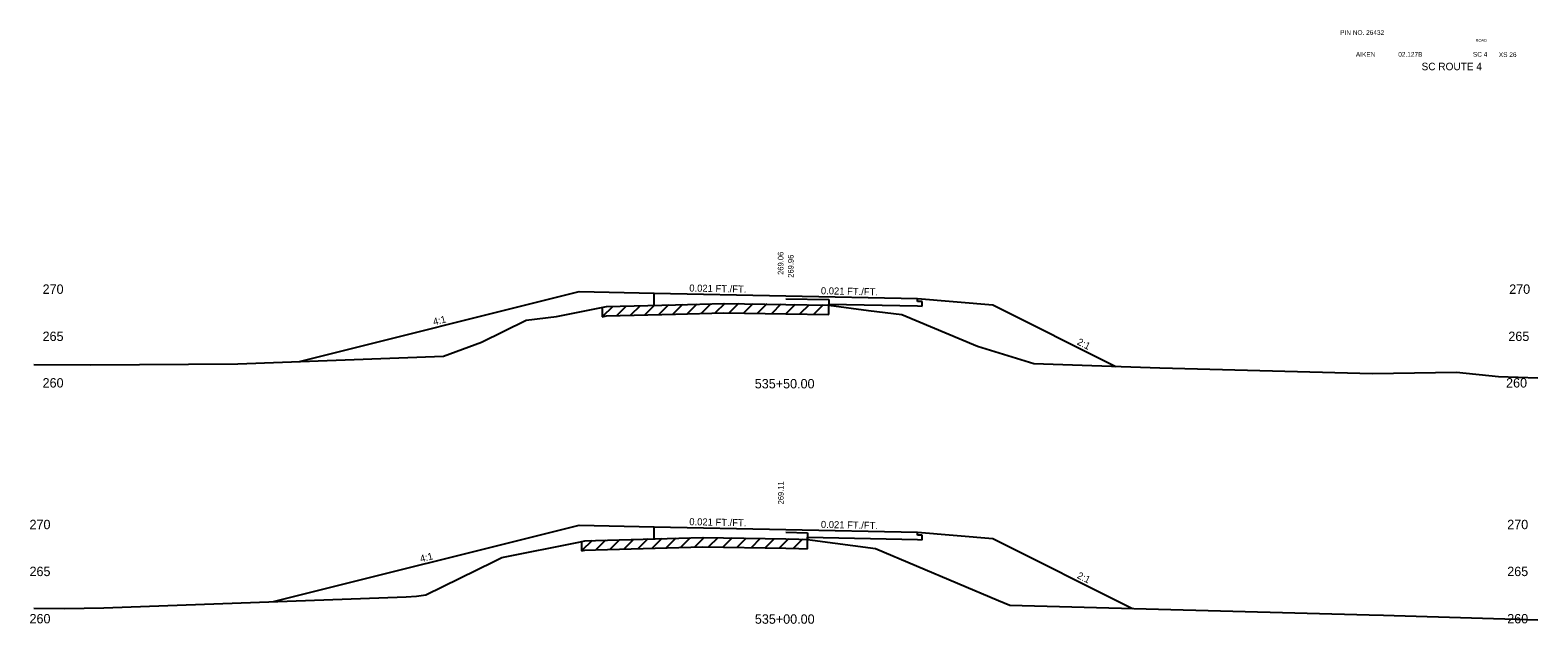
# Model space of a CAD drawing. Extents: x 883 to 1160, y 1002 to 4323.
# Drawn here: x 999.6 to 1160, y 3915.1 to 3978.2 of the extents above; entities that cross this region are included whole.
import ezdxf

# ---------------------------------------------------------------- set-up
doc = ezdxf.new("R2010")
doc.units = 0
for name, color, linetype in [('Level 1', 7, 'Continuous'), ('Level 10', 7, 'Continuous'), ('Level 11', 7, 'Continuous'), ('Level 12', 7, 'Continuous'), ('Level 3', 7, 'Continuous'), ('Level 32', 7, 'Continuous'), ('Level 53', 7, 'Continuous'), ('Level 59', 7, 'Continuous'), ('Level 6', 7, 'Continuous'), ('Level 60', 7, 'Continuous'), ('Level 61', 7, 'Continuous'), ('Level 7', 7, 'Continuous')]:
    doc.layers.add(name, color=color, linetype=linetype)

msp = doc.modelspace()

# ---------------------------------------------------------------- linework, layer by layer
at = {"layer": 'Level 11'}
for p, q in [((1066, 3948.96), (1066, 3950.26)), ((1094, 3949.37), (1094, 3949.67)), ((1094.5, 3949.36), (1094, 3949.37)), ((1094.5, 3948.88), (1094.5, 3949.36)), ((1094, 3948.89), (1094.5, 3948.88)), ((1066, 3924.12), (1066, 3925.4)), ((1094, 3924.52), (1094, 3924.82)), ((1094.5, 3924.5), (1094, 3924.52)), ((1094, 3924.04), (1094.5, 3924.02)), ((1094.5, 3924.02), (1094.5, 3924.5))]:
    msp.add_line(p, q, dxfattribs=at)
at = {"layer": 'Level 12'}
for p, q in [((1084.57, 3948.99), (1084.57, 3949.09)), ((1084.57, 3949.09), (1094, 3948.89)), ((1082.31, 3924.06), (1082.31, 3924.28)), ((1082.31, 3924.28), (1094, 3924.04))]:
    msp.add_line(p, q, dxfattribs=at)
at = {"layer": 'Level 53'}
for p, q in [((1080, 3949.66), (1084.57, 3949.57)), ((1084.57, 3949.57), (1084.57, 3948.99)), ((1080, 3924.81), (1082.31, 3924.76)), ((1082.31, 3924.76), (1082.31, 3924.06))]:
    msp.add_line(p, q, dxfattribs=at)
at = {"layer": 'Level 59'}
for p, q in [((1066, 3950.26), (1080, 3949.96)), ((1080, 3949.96), (1094, 3949.67)), ((1066, 3925.4), (1080, 3925.11)), ((1080, 3925.11), (1094, 3924.82))]:
    msp.add_line(p, q, dxfattribs=at)
at = {"layer": 'Level 6'}
for p, q in [((1058, 3950.42), (1066, 3950.26)), ((1094, 3949.67), (1102, 3949.01)), ((1058, 3925.56), (1066, 3925.4)), ((1094, 3924.82), (1102, 3924.15))]:
    msp.add_line(p, q, dxfattribs=at)
at = {"layer": 'Level 60'}
for p, q in [((1068.25, 3949.02), (1073.41, 3949.17)), ((1073.41, 3949.17), (1080, 3949.06)), ((1052.38, 3947.37), (1055.59, 3947.76)), ((1055.59, 3947.76), (1060.9, 3948.83)), ((1060.9, 3948.83), (1068.25, 3949.02)), ((1080, 3949.06), (1084.58, 3948.99)), ((1084.58, 3948.99), (1088.78, 3948.42)), ((1088.78, 3948.42), (1092.35, 3947.98)), ((1092.35, 3947.98), (1100.37, 3944.61)), ((1047.62, 3945.05), (1052.38, 3947.37)), ((1043.56, 3943.55), (1047.62, 3945.05)), ((1100.37, 3944.61), (1106.37, 3942.77)), ((1000, 3942.67), (1006, 3942.62)), ((1006, 3942.62), (1021.69, 3942.75)), ((1021.69, 3942.75), (1043.56, 3943.55)), ((1106.37, 3942.77), (1119.78, 3942.3)), ((1119.78, 3942.3), (1142.41, 3941.69)), ((1142.41, 3941.69), (1151.34, 3941.83)), ((1151.34, 3941.83), (1155.83, 3941.38)), ((1155.83, 3941.38), (1160, 3941.26)), ((1049.78, 3922.12), (1057.99, 3923.76)), ((1057.99, 3923.76), (1058.6, 3923.91)), ((1058.6, 3923.91), (1059.73, 3923.95)), ((1059.73, 3923.95), (1071.18, 3924.26)), ((1071.18, 3924.26), (1080, 3924.11)), ((1080, 3924.11), (1081.39, 3924.08)), ((1081.39, 3924.08), (1082.3, 3924.06)), ((1082.3, 3924.06), (1082.84, 3923.98)), ((1082.84, 3923.98), (1089.55, 3923.07)), ((1048.93, 3921.7), (1049.78, 3922.12)), ((1089.55, 3923.07), (1102.62, 3917.57)), ((1041.68, 3918.17), (1048.93, 3921.7)), ((1007.44, 3916.77), (1039.6, 3917.96)), ((1039.6, 3917.96), (1040.69, 3918.01)), ((1040.69, 3918.01), (1041.68, 3918.17)), ((1102.62, 3917.57), (1103.84, 3917.05)), ((1103.84, 3917.05), (1142.07, 3916.04)), ((1000, 3916.73), (1003.26, 3916.71)), ((1003.26, 3916.71), (1007.44, 3916.77)), ((1142.07, 3916.04), (1143.58, 3915.98)), ((1143.58, 3915.98), (1144.72, 3915.97)), ((1144.72, 3915.97), (1160, 3915.51))]:
    msp.add_line(p, q, dxfattribs=at)
at = {"layer": 'Level 61'}
for p, q in [((1070.51, 3949.09), (1069.48, 3948.06)), ((1072.01, 3949.13), (1070.98, 3948.1)), ((1073.51, 3949.17), (1072.48, 3948.15)), ((1074.97, 3949.15), (1073.98, 3948.16)), ((1076.47, 3949.12), (1075.49, 3948.14)), ((1077.97, 3949.1), (1076.99, 3948.11)), ((1079.47, 3949.07), (1078.49, 3948.09)), ((1061.58, 3948.84), (1060.47, 3947.74)), ((1060.47, 3948.74), (1060.47, 3947.74)), ((1060.47, 3947.74), (1060.9, 3947.83)), ((1060.9, 3947.83), (1068.25, 3948.02)), ((1063, 3948.88), (1061.97, 3947.85)), ((1064.5, 3948.92), (1063.48, 3947.9)), ((1066.01, 3948.96), (1064.98, 3947.94)), ((1067.51, 3949), (1066.48, 3947.98)), ((1069.01, 3949.05), (1067.98, 3948.02)), ((1068.25, 3948.02), (1073.41, 3948.17)), ((1073.41, 3948.17), (1080, 3948.06)), ((1080.97, 3949.04), (1079.99, 3948.06)), ((1080, 3948.06), (1084.57, 3947.99)), ((1082.48, 3949.02), (1081.49, 3948.04)), ((1083.98, 3949), (1082.99, 3948.01)), ((1084.57, 3947.99), (1084.57, 3948.99)), ((1059.38, 3923.94), (1058.27, 3922.83)), ((1058.27, 3923.83), (1058.27, 3922.83)), ((1060.8, 3923.98), (1059.77, 3922.95)), ((1062.3, 3924.02), (1061.27, 3922.99)), ((1063.8, 3924.06), (1062.77, 3923.03)), ((1065.3, 3924.1), (1064.27, 3923.07)), ((1066.8, 3924.14), (1065.77, 3923.11)), ((1068.3, 3924.18), (1067.28, 3923.15)), ((1069.81, 3924.22), (1068.78, 3923.19)), ((1071.3, 3924.26), (1070.28, 3923.24)), ((1072.76, 3924.23), (1071.78, 3923.25)), ((1074.27, 3924.21), (1073.28, 3923.22)), ((1075.77, 3924.18), (1074.78, 3923.2)), ((1077.27, 3924.15), (1076.29, 3923.17)), ((1078.77, 3924.13), (1077.79, 3923.15)), ((1080.27, 3924.1), (1079.29, 3923.12)), ((1081.77, 3924.07), (1080.79, 3923.09)), ((1082.31, 3923.06), (1082.31, 3924.06)), ((1058.27, 3922.83), (1058.6, 3922.91)), ((1058.6, 3922.91), (1059.73, 3922.95)), ((1059.73, 3922.95), (1071.18, 3923.26)), ((1071.18, 3923.26), (1080, 3923.11)), ((1080, 3923.11), (1081.39, 3923.08)), ((1081.39, 3923.08), (1082.3, 3923.06)), ((1082.3, 3923.06), (1082.31, 3923.06))]:
    msp.add_line(p, q, dxfattribs=at)
at = {"layer": 'Level 7'}
for p, q in [((1028.27, 3942.99), (1058, 3950.42)), ((1102, 3949.01), (1115.09, 3942.46)), ((1025.5, 3917.44), (1058, 3925.56)), ((1102, 3924.15), (1116.89, 3916.7))]:
    msp.add_line(p, q, dxfattribs=at)

# ---------------------------------------------------------------- texts
at = {"layer": 'Level 1'}
for s, height, p in [('PIN NO. 26432', 0.5, (1138.97, 3977.73)), ('AIKEN', 0.5, (1140.64, 3975.41)), ('02.127B', 0.5, (1145.15, 3975.41)), ('SC ROUTE 4', 0.8, (1147.63, 3973.97)), ('SC 4', 0.5, (1153.09, 3975.41)), ('XS 26', 0.5, (1155.85, 3975.38)), ('535+50.00', 1, (1076.69, 3940.12)), ('535+00.00', 1, (1076.7, 3915.08))]:
    msp.add_text(s, height=height, dxfattribs=at).set_placement(p)
at = {"layer": 'Level 10'}
for s, p in [('269.06', (1079.74, 3952.2)), ('269.11', (1079.76, 3927.78))]:
    msp.add_text(s, height=0.6, rotation=90, dxfattribs=at).set_placement(p)
at = {"layer": 'Level 3'}
for s, height, p in [('ROAD', 0.3, (1153.38, 3977)), (' 270', 1, (1000.55, 3950.18)), (' 270', 1, (1156.58, 3950.18)), (' 265', 1, (1000.55, 3945.16)), (' 265', 1, (1156.49, 3945.16)), (' 260', 1, (1000.55, 3940.21)), (' 260', 1, (1156.25, 3940.21)), (' 270', 1, (999.16, 3925.14)), (' 270', 1, (1156.37, 3925.14)), (' 265', 1, (999.16, 3920.15)), (' 265', 1, (1156.37, 3920.15)), (' 260', 1, (999.16, 3915.12)), (' 260', 1, (1156.37, 3915.12))]:
    msp.add_text(s, height=height, dxfattribs=at).set_placement(p)
at = {"layer": 'Level 32'}
for s, rotation, p in [('0.021 FT./FT.', 358.8084, (1069.72, 3950.43)), ('0.021 FT./FT.', 358.8084, (1083.72, 3950.14)), ('4:1', 14.0362, (1042.56, 3946.82)), ('2:1', 333.435, (1110.91, 3944.83)), ('0.021 FT./FT.', 358.8084, (1069.72, 3925.57)), ('0.021 FT./FT.', 358.8084, (1083.72, 3925.28)), ('4:1', 14.0362, (1041.17, 3921.61)), ('2:1', 333.435, (1110.91, 3919.97))]:
    msp.add_text(s, height=0.75, rotation=rotation, dxfattribs=at).set_placement(p)
at = {"layer": 'Level 59'}
msp.add_text(' 269.96', height=0.6, rotation=90, dxfattribs=at).set_placement((1080.82, 3951.67))

doc.saveas('drawing.dxf')
